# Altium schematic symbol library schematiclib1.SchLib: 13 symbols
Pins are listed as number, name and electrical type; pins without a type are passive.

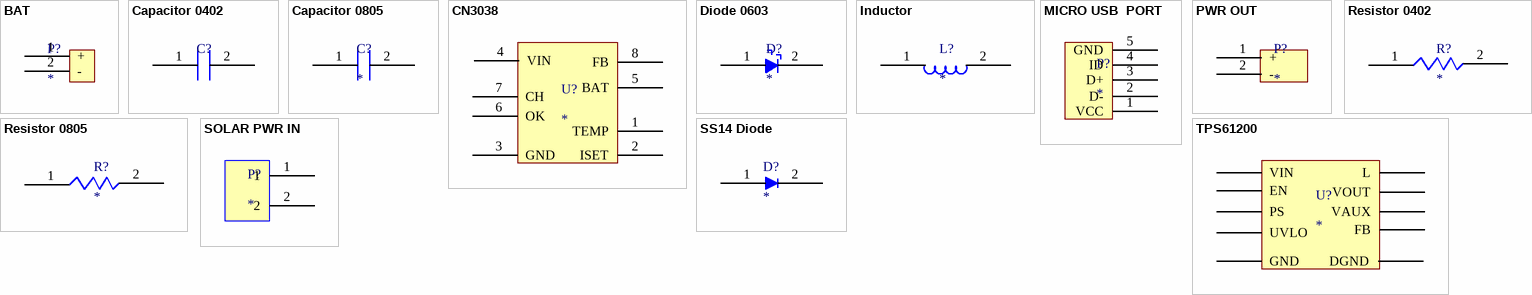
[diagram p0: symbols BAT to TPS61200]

## BAT
designator P?
footprint PWR
pins: 1 +, 2 -

## Capacitor 0402
designator C?
footprint Model Name (Footprint not found)
footprint CAPACITOR 0402
pins: 1, 2

## Capacitor 0805
designator C?
footprint CAPACITOR 0805
pins: 1, 2

## CN3038
designator U?
footprint CN3083
pins: 1 TEMP, 2 ISET, 3 GND, 4 VIN, 5 BAT, 6 OK, 7 CH, 8 FB

## Diode 0603
designator D?
footprint DIODE 0603
footprint DIODE 0603
pins: 1, 2

## Inductor
designator L?
LPS3015 - 222MRB
footprint LPS3015
pins: 1, 2

## MICRO USB  PORT
designator P?
footprint MICRO USB OUT
pins: 1 VCC, 2 D-, 3 D+, 4 ID, 5 GND

## PWR OUT
designator P?
footprint PWR
footprint Model Name (Footprint not found)
footprint PWR
pins: 1 +, 2 -

## Resistor 0402
designator R?
footprint RESISTOR 0402
pins: 1, 2

## Resistor 0805
designator R?
footprint RESISTOR 0805
pins: 1, 2

## SOLAR PWR IN
designator P?
footprint PWR
pins: 1, 2

## SS14 Diode
designator D?
footprint SS14
footprint SS14
pins: 1, 2

## TPS61200
designator U?
footprint TPS61200
pins: 1 VAUX, 2 VOUT, 3 L, 4 DGND, 5 VIN, 6 EN, 7 UVLO, 8 PS, 9 GND, 10 FB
